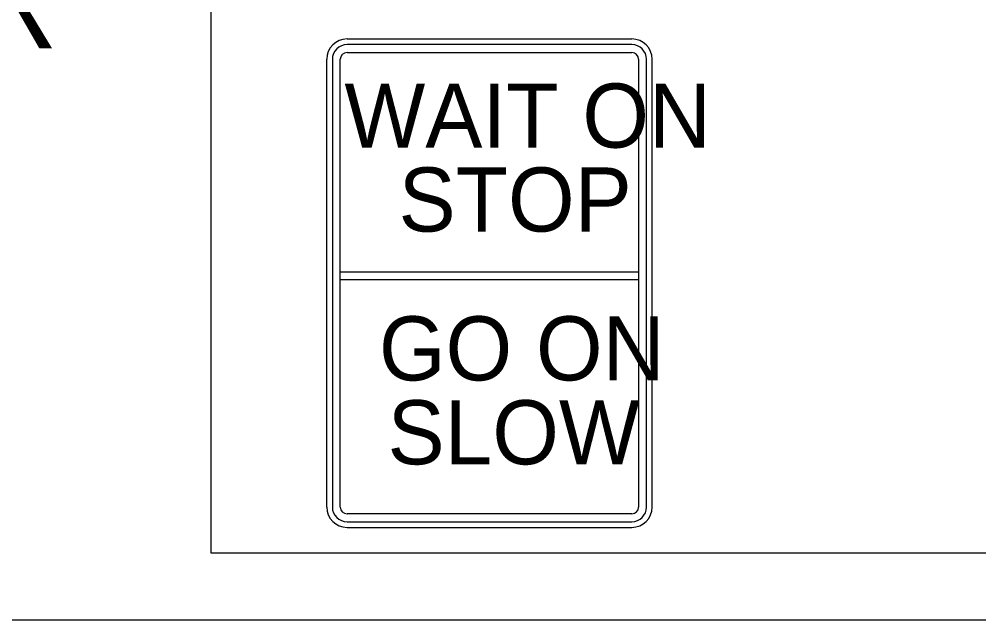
# Model space of a CAD drawing. Extents: x 21.7 to 29.1, y 5.9 to 16.2.
# Drawn here: x 27.525 to 28.39, y 13.017 to 13.558 of the extents above; entities that cross this region are included whole.
import ezdxf

# ---------------------------------------------------------------- set-up
doc = ezdxf.new("R2010")
doc.units = 0
for name, color, linetype in [('BORD-LINE', 7, 'Continuous'), ('DETL-LINE', 7, 'Continuous'), ('DETL-NOTE', 7, 'Continuous'), ('USER-BORD', 7, 'Continuous')]:
    doc.layers.add(name, color=color, linetype=linetype)

msp = doc.modelspace()

# ---------------------------------------------------------------- linework, layer by layer
at = {"layer": 'BORD-LINE'}
for p, q in [((27.82021, 13.54007), (28.07685, 13.54007)), ((27.80188, 13.11845), (27.80188, 13.52174)), ((28.09518, 13.11845), (28.09518, 13.52174)), ((27.82021, 13.10012), (28.07685, 13.10012))]:
    msp.add_line(p, q, dxfattribs=at)
for points in [[(28.07685, 13.53497), (27.82021, 13.53497)], [(27.82021, 13.52785), (28.07685, 13.52785)], [(27.80697, 13.52174), (27.80697, 13.45942)], [(27.8141, 13.45942), (27.8141, 13.52174)], [(28.08296, 13.52174), (28.08296, 13.11845)], [(28.09009, 13.11845), (28.09009, 13.52174)], [(27.80697, 13.45942), (27.80697, 13.44441), (27.80697, 13.11845)], [(27.8141, 13.11845), (27.8141, 13.45942)], [(28.07685, 13.11234), (27.82021, 13.11234)], [(27.82021, 13.10521), (28.07685, 13.10521)]]:
    msp.add_lwpolyline(points, dxfattribs=at)
for centre, radius, start, end in [((27.82021, 13.52174), 0.01833, 90, 180), ((28.07685, 13.52174), 0.01833, 0, 90), ((27.82021, 13.52174), 0.01324, 90, 180), ((27.82021, 13.52174), 0.00611, 90, 180), ((28.07685, 13.52174), 0.01324, 0, 90), ((28.07685, 13.52174), 0.00611, 0, 90), ((27.82021, 13.11845), 0.01833, 180, 270), ((27.82021, 13.11845), 0.01324, 180, 270), ((27.82021, 13.11845), 0.00611, 180, 270), ((28.07685, 13.11845), 0.01833, 270, 360), ((28.07685, 13.11845), 0.01324, 270, 360), ((28.07685, 13.11845), 0.00611, 270, 360)]:
    msp.add_arc(centre, radius, start, end, dxfattribs=at)
at = {"layer": 'DETL-LINE'}
for points in [[(25.80407, 13.01689), (28.97928, 13.01689), (28.97928, 14.33286), (25.80407, 14.33286)], [(28.97321, 14.14685), (25.80407, 14.14685), (25.80407, 13.01694), (28.97321, 13.01694)], [(27.69786, 14.09638), (28.91887, 14.09638), (28.91887, 13.07685), (27.69786, 13.07685)], [(27.8141, 13.3232), (27.8141, 13.33033), (28.08296, 13.33033), (28.08296, 13.3232)]]:
    msp.add_lwpolyline(points, close=True, dxfattribs=at)

# ---------------------------------------------------------------- texts
at = {"layer": 'DETL-NOTE'}
msp.add_text('OR', height=0.08, dxfattribs=at).set_placement((27.39884, 13.5316))
at = {"layer": 'USER-BORD'}
for s, p in [('WAIT ON', (27.81784, 13.44218)), ('STOP', (27.86662, 13.3666)), ('GO ON', (27.84894, 13.2325)), ('SLOW', (27.85669, 13.15691))]:
    msp.add_text(s, height=0.057738, dxfattribs=at).set_placement(p)

doc.saveas('drawing.dxf')
